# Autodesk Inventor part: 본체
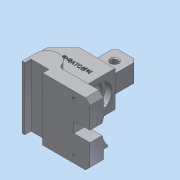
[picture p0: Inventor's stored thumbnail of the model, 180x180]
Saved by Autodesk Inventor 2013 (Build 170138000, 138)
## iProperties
Created: 2016-11
Part Number: 본체
Material: 알루미늄 6061
Document SubType Name: Modeling
Designer: dgall
Mass: 462.906 g
Surface Area: 317.29 cm^2
Volume: 170.814 cm^3
Density: 2.71 g/cm^3
Author: dgall
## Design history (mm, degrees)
sketch "스케치1"
  geometry: L1 (-8.5, 50)-(8.5, 50); L2 (12.5, 46)-(12.5, 20); L3 (17.5, 20)-(17.5, -20); L4 (17.5, -20)-(49.5, -20); L5 (49.5, -20)-(49.5, -40); L6 (49.5, -40)-(-3.5, -40); L7 (-3.5, -40)-(-3.5, -33); L8 (-3.5, -33)-(-23.5, -33); L9 (-23.5, -33)-(-23.5, -40); L10 (-23.5, -40)-(-26.5, -40); L11 (-26.5, -40)-(-26.5, -25); L12 (-26.5, -28)-(-36.5, -28); L13 (-40.5, -24)-(-40.5, 2); L14 (-40.5, 2)-(-22.5, 20); L15 (-22.5, 20)-(17.5, 20); L16 (-12.5, 20)-(-12.5, 46); L17 (49.5, -25)-(3.792, -25); L18 (8.5, 50)-(12.5, 46); L19 (-8.5, 50)-(-12.5, 46); L20 (-40.5, -24)-(-36.5, -28); A1 r 13 centre (-13.5, -25) between (-1.012, -21.389) and (-26.5, -25); A2 r 5 centre (3.792, -20) between (-1.012, -21.389) and (3.792, -25); 7 further points
  constraints: 40 end point, 12 parallel, 11 point on line, 5 point on circle, 4 horizontal alignment, 3 horizontal, 3 tangent, 2 centre point, 2 midpoint, 1 perpendicular, 1 vertical alignment
  dimensions: "d2" = 90 distance between parallel lines of L5 L13; "d3" = 5 distance between parallel lines of L3 L2; "d4" = 58 distance between parallel lines of L13 L3; "d6" = 48 distance between parallel lines of L12 L15; "d7" = 45 deg angle of L15 L14; "d8" = 18 horizontal distance of L14.end L13.end; "d9" = 3 distance of L9.end L10.end; "d10" = 7 distance between parallel lines of L10 L8; "d11" = 13 radius of A1; "d15" = 20 distance between parallel lines of L7 L9; "d16" = 5 radius of A2; "d17" = 15 distance between parallel lines of L6 L17; "d18" = 20 distance between parallel lines of L4 L6; "d19" = 63 distance from line of L5 A1.centre; "d20" = 90 distance between parallel lines of L6 L1; "d21" = 4 distance of L1.end point (12.5, 50); "d22" = 4 distance of L2.start point (12.5, 50) (= d21); "d23" = 4 distance of L1.start point (-12.5, 50) (= d21); "d24" = 4 distance of L16.end point (-12.5, 50) (= d23); "d25" = 4 distance of L13.start point (-40.5, -28); "d26" = 4 distance of L12.end point (-40.5, -28) (= d25); "d27" = 25 distance between parallel lines of L2 L16; "d28" = 60 distance between parallel lines of L10 L15
extrude "돌출1" new body sketch "스케치1" stored distance "d29" = 20; taper "d30" = 0 deg
extrude "돌출2" join sketch "스케치1" stored distance "d31" = 40; taper "d32" = 0 deg
extrude "돌출3" join sketch "스케치1" stored distance "d33" = 70; taper "d34" = 0 deg
sketch "스케치2"
  geometry: L1 (-40.5, -24)-(-40.5, 2) reference; L2 (17.5, 20)-(17.5, -20) reference; L3 (-40.5, 2)-(17.5, 2); L4 (-40.5, 2)-(-22.5, 20) reference; L5 (-26.5, -28)-(-36.5, -28) reference; L6 (17.5, -12.5)-(10.5, -12.5); L7 (10.5, -12.5)-(10.5, -9); L8 (9.5, -8)-(-40.5, -8); L9 (9.5, -8)-(10.5, -9); 1 further point
  constraints: 10 end point, 6 point on line, 3 perpendicular, 1 parallel
  dimensions: "d35" = 30 distance between parallel lines of L5 L3; "d41" = 7 distance of L6.start L6.end; "d42" = 29 diameter of L6 L3; "d43" = 20 diameter of L8 L3; "d44" = 1 distance of L8.start point (10.5, -8); "d45" = 1 distance of L7.end point (10.5, -8) (= d44)
revolve "회전1" sketch "스케치2" stored, may be unused: angle "d46" = 90 deg
sketch "스케치3"
  geometry: L1 (40, 0)-(0, 0) reference; L2 (-15, -20)-(55, -20) reference; L3 (14, -6.373)-(14, -20); L4 (26, -6.373)-(26, -20); C1 r 14.5 at (20, 22) reference; A1 r 29 centre (20, 22) between (1.106, 0) and (14, -6.373); A2 r 29 centre (20, 22) between (26, -6.373) and (38.894, 0); 1 further point
  constraints: 4 end point, 4 point on circle, 4 point on line, 2 centre point, 2 perpendicular, 1 coincident, 1 concentric, 1 horizontal alignment
  dimensions: "d50" = 12 distance between parallel lines of L4 L3; "d51" = 29 radius of A1
extrude "돌출4" cut sketch "스케치3" distance "d52" = 18; taper "d53" = 0 deg
sketch "스케치4"
  geometry: L1 (45.708, 40)-(0, 40) reference; L2 (45.708, 55)-(45.708, 40) reference; L3 (0, 55)-(45.708, 55) reference; L4 (0, 55)-(0, 40) reference; 3 further points
  constraints: 1 vertical alignment
  dimensions: "d54" = 55 distance of point (27.708, -7.5) point (27.708, 47.5); "d56" = 27.5 vertical distance of point (-3.792, 20) point (27.708, 47.5) (= 0.5 x d54); "d57" = 18 distance from line of L2 point (27.708, 47.5)
hole "구멍1" sketch "스케치4" at (27.708, 47.5), (27.708, -7.5) diameter "d58" = 3.242; stored, may be unused: countersink angle "d62" = 90 deg, drill point angle "d64" = 118 deg; dims "d59" = 6, "d60" = 4, "d61" = 2, "d63" = 8
sketch "스케치5"
  geometry: L1 (17.5, -20)-(17.5, 20) reference; L2 (17.5, 20)-(-22.5, 20) reference; 2 further points
  constraints: 1 other
  dimensions: "d65" = 25 distance from line of L1 point (-7.5, 2); "d66" = 18 distance from line of L2 point (-7.5, 2)
feature "엠보싱1" sketch "스케치5" dims "d67" = 0.5, "d68" = 0
node "작업 평면1"
sketch "스케치6"
  geometry: L1 (0, 0)-(0, -26) reference; L2 (20, -26)-(20, 0) reference; L3 (0, -9)-(20, -9); L4 (0, -5)-(20, -5); A1 r 10 centre (10, -44) between (20, -44) and (0, -44) reference; 1 further point
  constraints: 4 end point, 4 point on line, 2 perpendicular
  dimensions: "d69" = 35 distance from line of A1.centre L3; "d70" = 8 diameter of L4 L3
revolve "회전2" sketch "스케치6" stored, may be unused: angle "d71" = 90 deg
chamfer "모따기1" distance "d72" = 1; stored, may be unused: second distance "d73" = 2, angle "d74" = 45 deg
chamfer "모따기2" distance "d75" = 5; stored, may be unused: second distance "d76" = 2, angle "d77" = 45 deg
fillet "모깎기1" dims "d78" = 3
node "솔리드1"
node "투영된 루프1"
other parameters: "d47" = 58
